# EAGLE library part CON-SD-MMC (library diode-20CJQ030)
Various SD/MMC Connectors
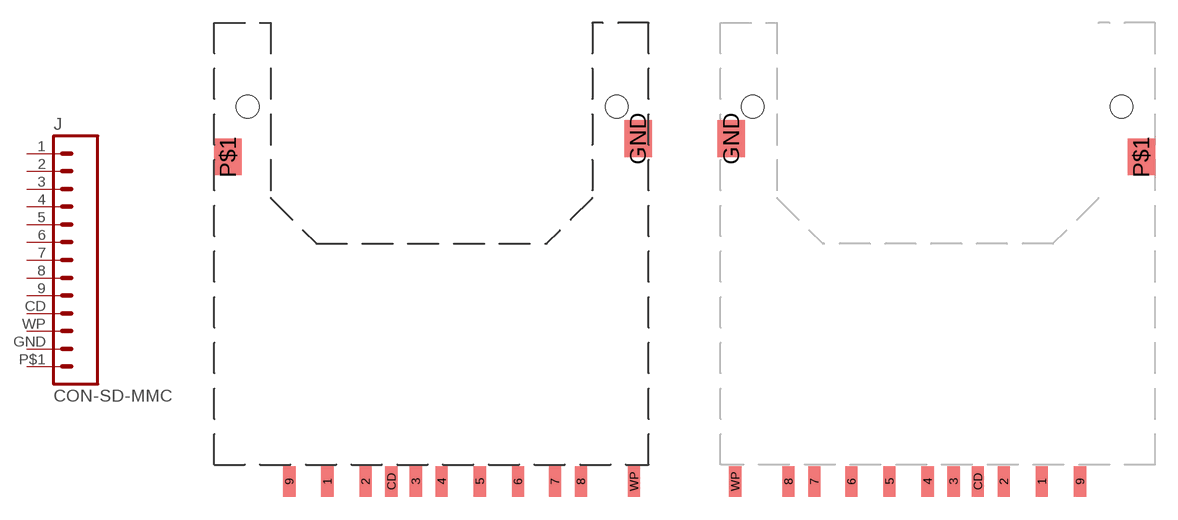
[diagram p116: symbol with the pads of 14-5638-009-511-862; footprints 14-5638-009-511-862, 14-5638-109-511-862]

Designator prefix J

## CON-SD-MMC-1  [14-5638-009-511-862]
1  1  pas
2  2  pas
3  3  pas
4  4  pas
5  5  pas
6  6  pas
7  7  pas
8  8  pas
9  9  pas
CD  CD  pas
GND  POL/GND  pas
P$1  SHIELD  pas
WP  WP  pas

## CON-SD-MMC-2  [14-5638-109-511-862]
Pads as for 14-5638-009-511-862

## CON-SD-MMC-3  [DM1AA-SF-PEJ(21)]
1  1  pas
2  2  pas
3  3  pas
4  4  pas
5  5  pas
6  6  pas
7  7  pas
8  8  pas
9  9  pas
CD  CD  pas
P$1  SHIELD  pas
POL  POL/GND  pas
WP  WP  pas

## Footprint 14-5638-009-511-862 (pad centres in mm)
AVX's 14-5638-009-511-862 Secure Digital Memory Card Connectors Series 5638 Spring Eject Type Normal Type Features: SD (Secure Digital) Memory Card technology is emerging as the next industry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
smd 0.8 x 2: 1 -6.88,-24.6; 2 -4.38,-24.6; 3 -1.08,-24.6; 4 0.62,-24.6; 5 3.12,-24.6; 6 5.62,-24.6; 7 8.05,-24.6; 8 9.75,-24.6; 9 -9.38,-24.6; CD -2.68,-24.6; WP 13.24,-24.6
smd 1.8 x 2.4: GND 13.5,-2.1; P$1 -13.4,-3.3
hole 1.5 at -12.1,0
hole 1.5 at 12.1,0

## Footprint 14-5638-109-511-862 (pad centres in mm)
AVX's 14-5638-109-511-862 Secure Digital Memory Card Connectors Series 5638 Spring Eject Type Reverse Type Features: SD (Secure Digital) Memory Card technology is emerging as the next industry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
smd 0.8 x 2: 1 6.88,-24.6; 2 4.38,-24.6; 3 1.08,-24.6; 4 -0.62,-24.6; 5 -3.12,-24.6; 6 -5.62,-24.6; 7 -8.05,-24.6; 8 -9.75,-24.6; 9 9.38,-24.6; CD 2.68,-24.6; WP -13.24,-24.6
smd 1.8 x 2.4: GND -13.5,-2.1; P$1 13.4,-3.3
hole 1.5 at 12.1,0
hole 1.5 at -12.1,0

## Footprint DM1AA-SF-PEJ(21) (pad centres in mm)
Hirose's DM1AA-SF-PEJ(21) SD Memory Card Connectors DM1 Series Features: 1. Withstands higher force of card insertion Metal cover extends over the back of the connector allowing it to withstand force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
smd 1.2 x 2: 1 6.775,2.2; 2 4.275,2.2; 3 1.775,2.2; 4 -0.725,2.2; 5 -3.225,2.2; 6 -5.725,2.2; 7 -8.15,2.2; 8 -9.85,2.2; 9 9.275,2.2
smd 2 x 1: CD -13.4,-9.2; POL -13.4,-20.75; WP -13.4,-18.15
smd 2 x 2: P$1 -13.8,-1.2; P$2 15.2,-1.2; P$3 15.2,-23.2; P$4 -13.8,-23.2
hole 1.3 at -11.2,0
hole 1.3 at 11.2,0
